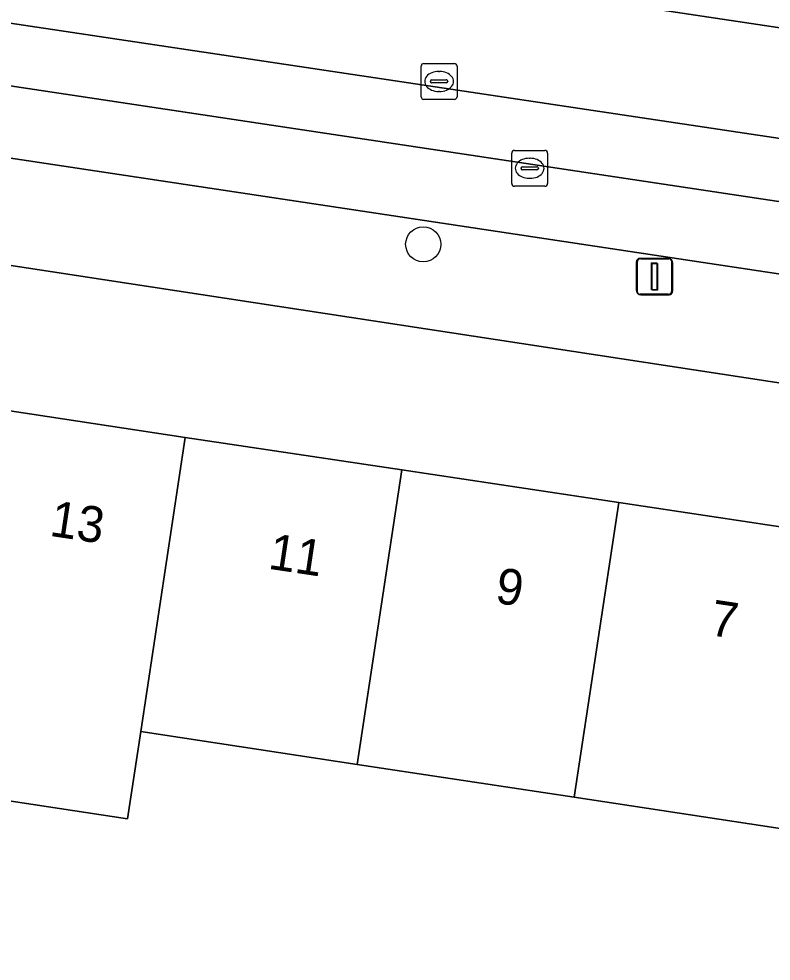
# Model space of a CAD drawing. Extents: x 163008 to 163854, y 382777 to 383982.
# Drawn here: x 163310.89 to 163331.87, y 383225.24 to 383251.53 of the extents above; entities that cross this region are included whole.
import ezdxf

# ---------------------------------------------------------------- set-up
doc = ezdxf.new("R2010")
doc.units = 0
for name, color, linetype in [('IMGEO_Boom', 7, 'Continuous'), ('IMGEO_Erf', 7, 'Continuous'), ('IMGEO_Kolk', 7, 'Continuous'), ('IMGEO_Lichtmast', 7, 'Continuous'), ('IMGEO_Pand', 7, 'Continuous'), ('IMGEO_Pand_nummerreeks', 7, 'Continuous'), ('IMGEO_Parkeervlak_open', 7, 'Continuous'), ('IMGEO_Rijbaan_lokaal_gesloten', 7, 'Continuous'), ('IMGEO_Rijbaan_lokaal_open', 7, 'Continuous'), ('IMGEO_Rioolput', 7, 'Continuous'), ('IMGEO_Voetpad_open', 7, 'Continuous')]:
    doc.layers.add(name, color=color, linetype=linetype)

msp = doc.modelspace()

# ---------------------------------------------------------------- linework, layer by layer
at = {"layer": 'IMGEO_Boom'}
msp.add_circle((163322.167, 383245.241), 0.489, dxfattribs=at)
at = {"layer": 'IMGEO_Erf'}
msp.add_lwpolyline([(163354.474, 383236.052), (163353.059, 383236.624), (163353.206, 383238.156), (163345.585, 383239.307), (163297.404, 383246.677), (163297.157, 383245.389), (163295.515, 383245.185), (163295.019, 383241.608), (163303.346, 383240.347), (163303.515, 383241.462), (163303.228, 383241.506), (163303.258, 383241.703), (163303.964, 383241.597), (163309.533, 383240.758), (163315.535, 383239.854), (163321.569, 383238.946), (163327.623, 383238.034), (163333.674, 383237.123), (163339.577, 383236.234), (163346.045, 383235.26), (163346.015, 383235.063), (163345.729, 383235.107), (163345.368, 383233.854), (163353.959, 383232.549)], close=True, dxfattribs=at)
msp.add_lwpolyline([(163349.416, 383224.687), (163349.813, 383227.404), (163344.766, 383228.148), (163344.662, 383228.163), (163344.474, 383227.073), (163338.329, 383228.004), (163337.983, 383225.717), (163335.394, 383226.109), (163335.74, 383228.396), (163332.427, 383228.898), (163326.377, 383229.815), (163320.324, 383230.732), (163314.29, 383231.646), (163313.922, 383229.211), (163307.922, 383230.12)], dxfattribs=at)
at = {"layer": 'IMGEO_Kolk'}
for p, q in [((163324.635, 383246.935), (163324.635, 383247.787)), ((163324.71, 383247.861), (163325.562, 383247.861)), ((163325.636, 383247.787), (163325.636, 383246.935)), ((163324.937, 383247.404), (163325.335, 383247.404)), ((163325.123, 383247.641), (163325.148, 383247.641)), ((163324.894, 383247.355), (163324.894, 383247.367)), ((163325.332, 383247.318), (163324.934, 383247.318)), ((163325.378, 383247.367), (163325.378, 383247.355)), ((163325.562, 383246.861), (163324.71, 383246.861)), ((163325.146, 383247.081), (163325.121, 383247.081))]:
    msp.add_line(p, q, dxfattribs=at)
for points in [[(163324.635, 383246.935), (163324.635, 383247.787)], [(163324.71, 383247.861), (163325.562, 383247.861)], [(163325.636, 383247.787), (163325.636, 383246.935)], [(163325.562, 383246.861), (163324.71, 383246.861)]]:
    msp.add_lwpolyline(points, dxfattribs=at)
for centre, radius, start, end in [((163324.712, 383247.785), 0.0765, 91.552, 178.448), ((163324.712, 383247.785), 0.0765, 91.552, 178.448), ((163325.56, 383247.785), 0.0765, 1.552, 88.448), ((163325.56, 383247.785), 0.0765, 1.552, 88.448), ((163324.934, 383247.364), 0.0403, 85.8775, 175.7526), ((163325.339, 383247.366), 0.0386, 1.7309, 96.639), ((163324.931, 383247.354), 0.0366, 178.938, 274.7102), ((163325.335, 383247.361), 0.043, 264.8664, 352.4533), ((163324.712, 383246.937), 0.0765, 181.552, 268.448), ((163324.712, 383246.937), 0.0765, 181.552, 268.448), ((163325.56, 383246.937), 0.0765, 271.552, 358.448), ((163325.56, 383246.937), 0.0765, 271.552, 358.448)]:
    msp.add_arc(centre, radius, start, end, dxfattribs=at)
for centre, major_axis, ratio, start_param, end_param in [((163325.122, 383247.361), (-0.387, 0.002), 0.722429, 4.712389, 7.853982), ((163325.147, 383247.361), (-0.39, 0.002), 0.717154, 1.570796, 4.712389)]:
    msp.add_ellipse(centre, major_axis=major_axis, ratio=ratio, start_param=start_param, end_param=end_param, dxfattribs=at)
at = {"layer": 'IMGEO_Lichtmast'}
for p, q in [((163328.211, 383244.849), (163329.001, 383244.849)), ((163329.001, 383244.849), (163328.211, 383244.849)), ((163328.232, 383244.833), (163329.022, 383244.833)), ((163329.022, 383244.833), (163328.232, 383244.833)), ((163328.111, 383243.949), (163328.111, 383244.749)), ((163328.111, 383244.749), (163328.111, 383243.949)), ((163328.132, 383243.933), (163328.132, 383244.733)), ((163328.132, 383244.733), (163328.132, 383243.933)), ((163329.101, 383244.749), (163329.101, 383243.949)), ((163329.101, 383243.949), (163329.101, 383244.749)), ((163329.122, 383244.733), (163329.122, 383243.933)), ((163329.122, 383243.933), (163329.122, 383244.733)), ((163329.001, 383243.849), (163328.211, 383243.849)), ((163328.211, 383243.849), (163329.001, 383243.849)), ((163329.022, 383243.833), (163328.232, 383243.833)), ((163328.232, 383243.833), (163329.022, 383243.833))]:
    msp.add_line(p, q, dxfattribs=at)
for points in [[(163328.531, 383244.724), (163328.681, 383244.724), (163328.681, 383243.974), (163328.531, 383243.974), (163328.531, 383244.724)], [(163328.552, 383244.708), (163328.702, 383244.708), (163328.702, 383243.958), (163328.552, 383243.958), (163328.552, 383244.708)]]:
    msp.add_lwpolyline(points, dxfattribs=at)
for centre, start, end in [((163328.211, 383244.749), 90, 180), ((163328.211, 383244.749), 90, 180), ((163328.232, 383244.733), 90, 180), ((163328.232, 383244.733), 90, 180), ((163329.001, 383244.749), 0, 90), ((163329.001, 383244.749), 360, 90), ((163329.022, 383244.733), 0, 90), ((163329.022, 383244.733), 360, 90), ((163328.211, 383243.949), 180, 270), ((163328.211, 383243.949), 180, 270), ((163328.232, 383243.933), 180, 270), ((163328.232, 383243.933), 180, 270), ((163329.001, 383243.949), 270, 0), ((163329.001, 383243.949), 270, 0), ((163329.022, 383243.933), 270, 0), ((163329.022, 383243.933), 270, 0)]:
    msp.add_arc(centre, 0.1, start, end, dxfattribs=at)
at = {"layer": 'IMGEO_Pand'}
for points in [[(163315.535, 383239.854), (163309.533, 383240.758), (163308.29, 383232.555), (163307.922, 383230.12), (163313.922, 383229.211), (163314.29, 383231.646)], [(163315.535, 383239.854), (163314.29, 383231.646), (163320.324, 383230.732), (163321.569, 383238.946)], [(163321.569, 383238.946), (163320.324, 383230.732), (163326.377, 383229.815), (163327.623, 383238.034)], [(163333.674, 383237.123), (163327.623, 383238.034), (163326.377, 383229.815), (163332.427, 383228.898)]]:
    msp.add_lwpolyline(points, close=True, dxfattribs=at)
at = {"layer": 'IMGEO_Parkeervlak_open'}
for points in [[(163352.362, 383243.049), (163352.333, 383243.384), (163297.236, 383251.684)], [(163299.93, 383249.264), (163349.531, 383241.782)]]:
    msp.add_lwpolyline(points, dxfattribs=at)
at = {"layer": 'IMGEO_Rijbaan_lokaal_gesloten'}
for points in [[(163285.184, 383258.317), (163352.91, 383248.164), (163353.412, 383249.506), (163352.608, 383249.943), (163288.229, 383259.608), (163286.363, 383259.893), (163285.467, 383260.115)], [(163352.593, 383245.12), (163297.241, 383253.428), (163297.016, 383251.731), (163297.236, 383251.684), (163352.333, 383243.384)]]:
    msp.add_lwpolyline(points, close=True, dxfattribs=at)
at = {"layer": 'IMGEO_Rijbaan_lokaal_open'}
msp.add_lwpolyline([(163285.184, 383258.317), (163284.361, 383253.616), (163296.886, 383251.754), (163297.016, 383251.731), (163297.241, 383253.428), (163352.593, 383245.12), (163352.91, 383248.164)], close=True, dxfattribs=at)
at = {"layer": 'IMGEO_Rioolput'}
for p, q in [((163322.185, 383250.285), (163323.037, 383250.285)), ((163322.11, 383249.359), (163322.11, 383250.211)), ((163322.598, 383250.065), (163322.623, 383250.065)), ((163323.111, 383250.211), (163323.111, 383249.359)), ((163322.369, 383249.779), (163322.369, 383249.791)), ((163322.412, 383249.828), (163322.81, 383249.828)), ((163322.853, 383249.791), (163322.853, 383249.779)), ((163322.807, 383249.742), (163322.409, 383249.742)), ((163322.621, 383249.505), (163322.596, 383249.505)), ((163323.037, 383249.285), (163322.185, 383249.285))]:
    msp.add_line(p, q, dxfattribs=at)
for points in [[(163322.185, 383250.285), (163323.037, 383250.285)], [(163322.11, 383249.359), (163322.11, 383250.211)], [(163323.111, 383250.211), (163323.111, 383249.359)], [(163323.037, 383249.285), (163322.185, 383249.285)]]:
    msp.add_lwpolyline(points, dxfattribs=at)
for centre, radius, start, end in [((163322.187, 383250.209), 0.0765, 91.552, 178.448), ((163322.187, 383250.209), 0.0765, 91.552, 178.448), ((163323.035, 383250.209), 0.0765, 1.552, 88.448), ((163323.035, 383250.209), 0.0765, 1.552, 88.448), ((163322.409, 383249.788), 0.0403, 85.8775, 175.7526), ((163322.406, 383249.778), 0.0366, 178.938, 274.7102), ((163322.81, 383249.785), 0.043, 264.8664, 352.4533), ((163322.814, 383249.79), 0.0386, 1.7309, 96.639), ((163322.187, 383249.361), 0.0765, 181.552, 268.448), ((163322.187, 383249.361), 0.0765, 181.552, 268.448), ((163323.035, 383249.361), 0.0765, 271.552, 358.448), ((163323.035, 383249.361), 0.0765, 271.552, 358.448)]:
    msp.add_arc(centre, radius, start, end, dxfattribs=at)
for centre, major_axis, ratio, start_param, end_param in [((163322.597, 383249.785), (-0.387, 0.002), 0.722429, 4.712389, 7.853982), ((163322.622, 383249.785), (-0.39, 0.002), 0.717154, 1.570796, 4.712389)]:
    msp.add_ellipse(centre, major_axis=major_axis, ratio=ratio, start_param=start_param, end_param=end_param, dxfattribs=at)
at = {"layer": 'IMGEO_Voetpad_open'}
for points in [[(163349.531, 383241.782), (163299.93, 383249.264)], [(163292.776, 383248.944), (163292.509, 383247.462), (163297.404, 383246.677), (163345.585, 383239.307), (163353.206, 383238.156), (163359.594, 383237.191)]]:
    msp.add_lwpolyline(points, dxfattribs=at)

# ---------------------------------------------------------------- texts
at = {"layer": 'IMGEO_Pand_nummerreeks'}
for s, p in [('13', (163311.723, 383237.111)), ('11', (163317.819, 383236.193)), ('9', (163324.144, 383235.242)), ('7', (163330.128, 383234.341))]:
    msp.add_text(s, height=1, rotation=351.4366, dxfattribs=at).set_placement(p)

doc.saveas('drawing.dxf')
